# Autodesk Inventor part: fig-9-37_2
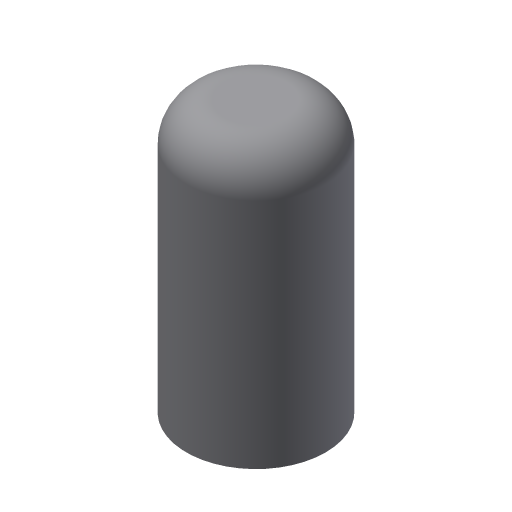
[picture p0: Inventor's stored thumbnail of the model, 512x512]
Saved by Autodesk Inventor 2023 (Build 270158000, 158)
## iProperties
Created: 2013-03
Part Number: fig-9-37_2
Material: Generic
Document SubType Name: Modeling
Designer: CADCIM
Density: 1 g/cm^3
Appearance: Default
Author: CADCIM
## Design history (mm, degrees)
sketch "Sketch1"
  geometry: C1 r 9 at (0, 0); 1 further point
  constraints: 1 centre point, 1 coincident
  dimensions: "d0" = 18 diameter of C1
extrude "Extrusion1" new body sketch "Sketch1" distance "d2" = 35; taper "d3" = 0 deg
fillet "Fillet1" dims "d4" = 5
body "Solid1"
